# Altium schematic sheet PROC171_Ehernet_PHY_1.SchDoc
size 431 x 279 mm; Date: Not shown in title block; ApprovedBy: Not shown in title block; CheckedBy: Not shown in title block; Author: Not shown in title block; CompanyName: Not shown in title block; Engineer: Not shown in title block; Organization: Not shown in title block; Address1: Not shown in title block; Address2: Not shown in title block; Address3: Not shown in title block; Address4: Not shown in title block; DocumentNumber: 16; Revision: Use project parameter SCH_Rev; SheetNumber: 16; SheetTotal: 26; PageSetup: Record=PageOptions¦CenterHorizontal=True¦CenterVertical=True¦PrintScale=1.00¦XCorrection=1.00¦YCorrection=1.00¦PrintKind=0¦BorderSize=5000000¦LeftOffset=0¦BottomOffset=0¦Orientation=2¦PaperLength=1000¦PaperWidth=1000¦Scale=100¦PaperSource=15¦PrintQuality=600¦MediaType=1¦DitherType=10¦PaperKind=Letter¦PrintScaleMode=1
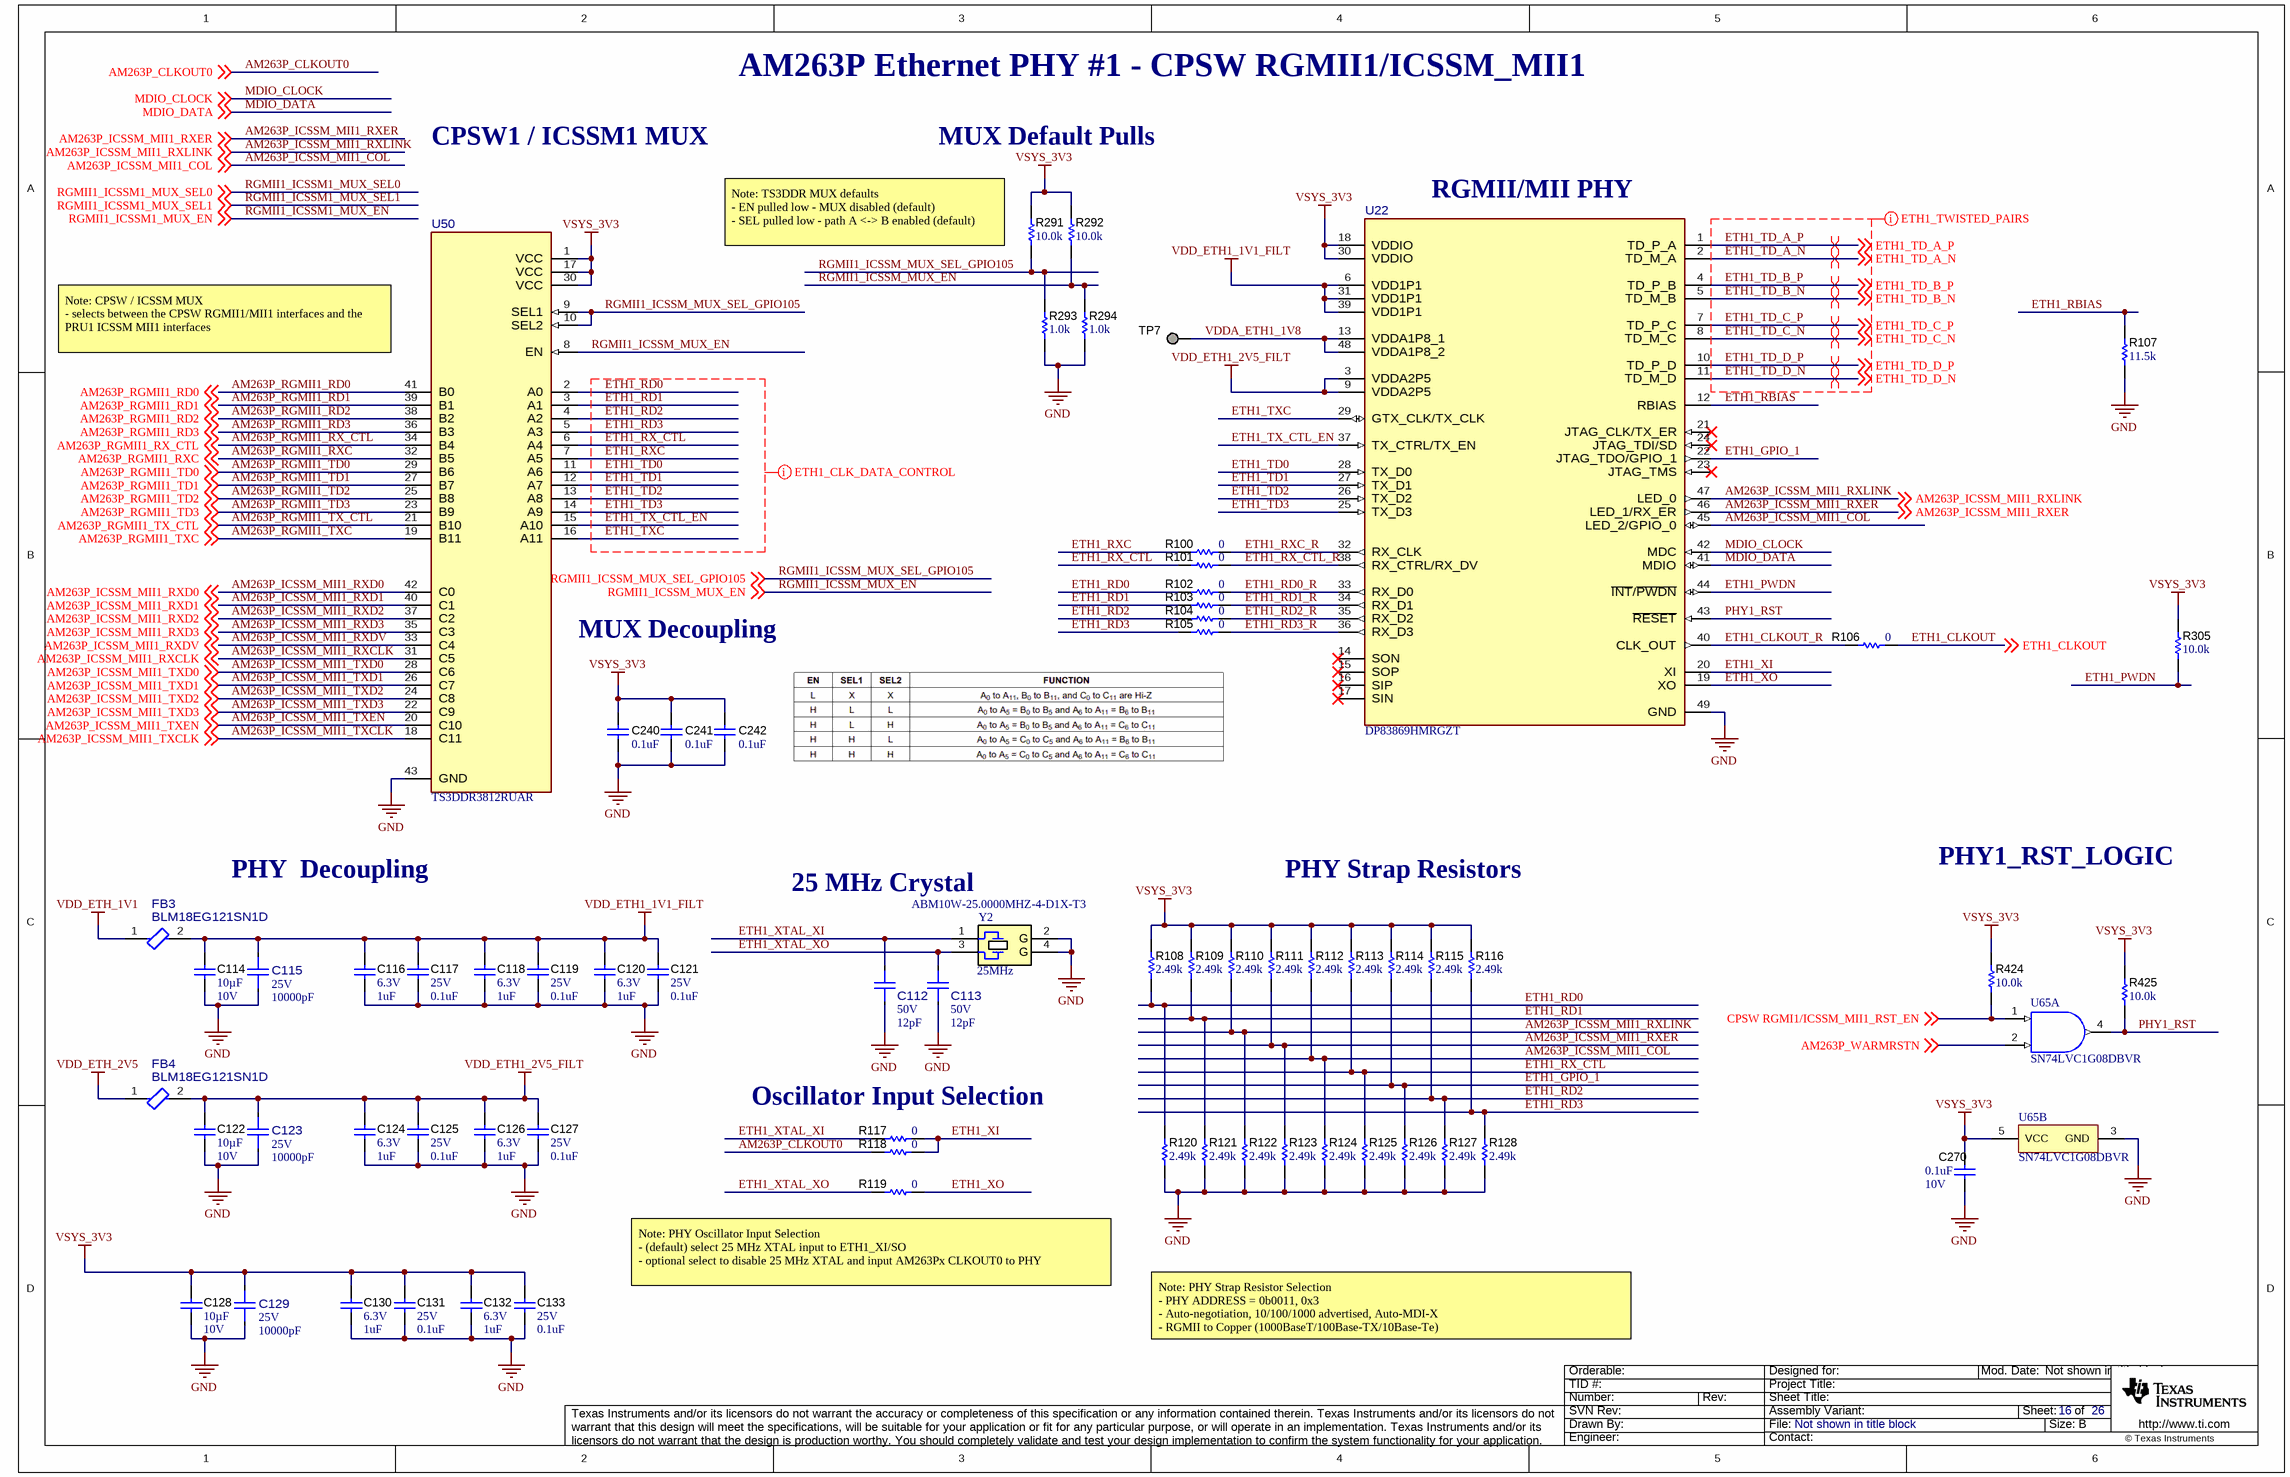
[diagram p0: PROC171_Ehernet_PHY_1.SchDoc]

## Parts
C112  VDC_V: 50V  ValueDisplayed: 12pF  [FP-GJM1555C1H120JB01D_0402-MFG]  (hidden comment: GJM1555C1H120JB01D)
C113  VDC_V: 50V  ValueDisplayed: 12pF  [FP-GJM1555C1H120JB01D_0402-MFG]  (hidden comment: GJM1555C1H120JB01D)
C114  Cap_F: 10µF  VDC_V: 10V  [0603]  (hidden comment: GRM188Z71A106MA73D)
C115  VDC_V: 25V  ValueDisplayed: 10000pF  [FP-GRM1555C1E103JE01D_0402-MFG]  (hidden comment: GRM1555C1E103JE01D)
C116  VDC_V: 6.3V  ValueDisplayed: 1uF  [0402]  (hidden comment: GRM155R70J105MA12D)
C117  VDC_V: 25V  ValueDisplayed: 0.1uF  [0402]  (hidden comment: GRM155R71E104KE14D)
C118  VDC_V: 6.3V  ValueDisplayed: 1uF  [0402]  (hidden comment: GRM155R70J105MA12D)
C119  VDC_V: 25V  ValueDisplayed: 0.1uF  [0402]  (hidden comment: GRM155R71E104KE14D)
C120  VDC_V: 6.3V  ValueDisplayed: 1uF  [0402]  (hidden comment: GRM155R70J105MA12D)
C121  VDC_V: 25V  ValueDisplayed: 0.1uF  [0402]  (hidden comment: GRM155R71E104KE14D)
C122  Cap_F: 10µF  VDC_V: 10V  [0603]  (hidden comment: GRM188Z71A106MA73D)
C123  VDC_V: 25V  ValueDisplayed: 10000pF  [FP-GRM1555C1E103JE01D_0402-MFG]  (hidden comment: GRM1555C1E103JE01D)
C124  VDC_V: 6.3V  ValueDisplayed: 1uF  [0402]  (hidden comment: GRM155R70J105MA12D)
C125  VDC_V: 25V  ValueDisplayed: 0.1uF  [0402]  (hidden comment: GRM155R71E104KE14D)
C126  VDC_V: 6.3V  ValueDisplayed: 1uF  [0402]  (hidden comment: GRM155R70J105MA12D)
C127  VDC_V: 25V  ValueDisplayed: 0.1uF  [0402]  (hidden comment: GRM155R71E104KE14D)
C128  Cap_F: 10µF  VDC_V: 10V  [0603]  (hidden comment: GRM188Z71A106MA73D)
C129  VDC_V: 25V  ValueDisplayed: 10000pF  [FP-GRM1555C1E103JE01D_0402-MFG]  (hidden comment: GRM1555C1E103JE01D)
C130  VDC_V: 6.3V  ValueDisplayed: 1uF  [0402]  (hidden comment: GRM155R70J105MA12D)
C131  VDC_V: 25V  ValueDisplayed: 0.1uF  [0402]  (hidden comment: GRM155R71E104KE14D)
C132  VDC_V: 6.3V  ValueDisplayed: 1uF  [0402]  (hidden comment: GRM155R70J105MA12D)
C133  VDC_V: 25V  ValueDisplayed: 0.1uF  [0402]  (hidden comment: GRM155R71E104KE14D)
C240  ValueDisplayed: 0.1uF  [0402]  (hidden comment: GRM155R71E104KE14D)
C241  ValueDisplayed: 0.1uF  [0402]  (hidden comment: GRM155R71E104KE14D)
C242  ValueDisplayed: 0.1uF  [0402]  (hidden comment: GRM155R71E104KE14D)
C270  VDC_V: 10V  ValueDisplayed: 0.1uF  [0402]  (hidden comment: 885012105010)
FB3  BLM18EG121SN1D  [FP-BLM18EG121SN1D_0603-MFG]
FB4  BLM18EG121SN1D  [FP-BLM18EG121SN1D_0603-MFG]
R100  ValueDisplayed: 0  [0402]  (hidden comment: ERJ-2GE0R00X)
R101  ValueDisplayed: 0  [0402]  (hidden comment: ERJ-2GE0R00X)
R102  ValueDisplayed: 0  [0402]  (hidden comment: ERJ-2GE0R00X)
R103  ValueDisplayed: 0  [0402]  (hidden comment: ERJ-2GE0R00X)
R104  ValueDisplayed: 0  [0402]  (hidden comment: ERJ-2GE0R00X)
R105  ValueDisplayed: 0  [0402]  (hidden comment: ERJ-2GE0R00X)
R106  ValueDisplayed: 0  [0402]  (hidden comment: ERJ-2GE0R00X)
R107  ValueDisplayed: 11.5k  [0402]  (hidden comment: ERJ-2RKF1152X)
R108  ValueDisplayed: 2.49k  [0402]  (hidden comment: CRCW04022K49FKED)
R109  ValueDisplayed: 2.49k  [0402]  (hidden comment: CRCW04022K49FKED)
R110  ValueDisplayed: 2.49k  [0402]  (hidden comment: CRCW04022K49FKED)
R111  ValueDisplayed: 2.49k  [0402]  (hidden comment: CRCW04022K49FKED)
R112  ValueDisplayed: 2.49k  [0402]  (hidden comment: CRCW04022K49FKED)
R113  ValueDisplayed: 2.49k  [0402]  (hidden comment: CRCW04022K49FKED)
R114  ValueDisplayed: 2.49k  [0402]  (hidden comment: CRCW04022K49FKED)
R115  ValueDisplayed: 2.49k  [0402]  (hidden comment: CRCW04022K49FKED)
R116  ValueDisplayed: 2.49k  [0402]  (hidden comment: CRCW04022K49FKED)
R117  ValueDisplayed: 0  [0402]  (hidden comment: ERJ-2GE0R00X)
R118  ValueDisplayed: 0  [0402]  (hidden comment: ERJ-2GE0R00X)
R119  ValueDisplayed: 0  [0402]  (hidden comment: ERJ-2GE0R00X)
R120  ValueDisplayed: 2.49k  [0402]  (hidden comment: CRCW04022K49FKED)
R121  ValueDisplayed: 2.49k  [0402]  (hidden comment: CRCW04022K49FKED)
R122  ValueDisplayed: 2.49k  [0402]  (hidden comment: CRCW04022K49FKED)
R123  ValueDisplayed: 2.49k  [0402]  (hidden comment: CRCW04022K49FKED)
R124  ValueDisplayed: 2.49k  [0402]  (hidden comment: CRCW04022K49FKED)
R125  ValueDisplayed: 2.49k  [0402]  (hidden comment: CRCW04022K49FKED)
R126  ValueDisplayed: 2.49k  [0402]  (hidden comment: CRCW04022K49FKED)
R127  ValueDisplayed: 2.49k  [0402]  (hidden comment: CRCW04022K49FKED)
R128  ValueDisplayed: 2.49k  [0402]  (hidden comment: CRCW04022K49FKED)
R291  ValueDisplayed: 10.0k  [0402]  (hidden comment: ERJ-2RKF1002X)
R292  ValueDisplayed: 10.0k  [0402]  (hidden comment: ERJ-2RKF1002X)
R293  ValueDisplayed: 1.0k  [0402]  (hidden comment: ERJ-2GEJ102X)
R294  ValueDisplayed: 1.0k  [0402]  (hidden comment: ERJ-2GEJ102X)
R305  ValueDisplayed: 10.0k  [0402]  (hidden comment: ERJ-2RKF1002X)
R424  ValueDisplayed: 10.0k  [0402]  (hidden comment: ERJ-2RKF1002X)
R425  ValueDisplayed: 10.0k  [0402L]  (hidden comment: CRCW040210K0FKED)
TP7  TESTPOINT  [TP_25MIL-SMT]  (value not drawn)  (no BOM)
U22  DP83869HMRGZT  [RGZ0048B-MFG]
U50  TS3DDR3812RUAR  [RUA0042A-MFG]
U65  SN74LVC1G08DBVR  [DBV0005A_N]  (parts A,B of 2)
Y2  Frequency_Fixed: 25MHz  [Abracon_ABM10W]  (hidden comment: ABM10W-25.0000MHZ-4-D1X-T3)

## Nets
GND: C112.1 C113.1 C114.2 C115.1 C116.2 C117.2 C118.2 C119.2 C120.2 C121.2 C122.2 C123.1 C124.2 C125.2 C126.2 C127.2 C128.2 C129.1 C130.2 C131.2 C132.2 C133.2 C240.1 C241.1 C242.1 C270.2 R107.1 R120.1 R121.1 R122.1 R123.1 R124.1 R125.1 R126.1 R127.1 R128.1 R293.1 R294.1 U22.49(GND) U50.43(GND) U65.3(GND) Y2.2(GND) Y2.4(GND)
VDD_ETH1_1V1_FILT: C114.1 C115.2 C116.1 C117.1 C118.1 C119.1 C120.1 C121.1 FB3.2 U22.6(VDD1P1) U22.31(VDD1P1) U22.39(VDD1P1)
VDD_ETH1_2V5_FILT: C122.1 C123.2 C124.1 C125.1 C126.1 C127.1 FB4.2 U22.3(VDDA2P5) U22.9(VDDA2P5)
VDD_ETH_1V1: FB3.1
VDD_ETH_2V5: FB4.1
VSYS_3V3: C128.1 C129.2 C130.1 C131.1 C132.1 C133.1 C240.2 C241.2 C242.2 C270.1 R108.2 R109.2 R110.2 R111.2 R112.2 R113.2 R114.2 R115.2 R116.2 R291.1 R292.1 R305.1 R424.1 R425.2 U22.18(VDDIO) U22.30(VDDIO) U50.1(VCC) U50.17(VCC) U50.30(VCC) U65.5(VCC)
AM263P_CLKOUT0: R118.1 ; off-sheet AM263P_CLKOUT0
AM263P_ICSSM_MII1_COL: R112.1 R124.2 U22.45(LED_2/GPIO_0) ; off-sheet AM263P_ICSSM_MII1_COL
AM263P_ICSSM_MII1_RXCLK: U50.31(C5) ; off-sheet AM263P_ICSSM_MII1_RXCLK
AM263P_ICSSM_MII1_RXD0: U50.42(C0) ; off-sheet AM263P_ICSSM_MII1_RXD0
AM263P_ICSSM_MII1_RXD1: U50.40(C1) ; off-sheet AM263P_ICSSM_MII1_RXD1
AM263P_ICSSM_MII1_RXD2: U50.37(C2) ; off-sheet AM263P_ICSSM_MII1_RXD2
AM263P_ICSSM_MII1_RXD3: U50.35(C3) ; off-sheet AM263P_ICSSM_MII1_RXD3
AM263P_ICSSM_MII1_RXDV: U50.33(C4) ; off-sheet AM263P_ICSSM_MII1_RXDV
AM263P_ICSSM_MII1_RXER: R111.1 R123.2 U22.46(LED_1/RX_ER) ; off-sheet AM263P_ICSSM_MII1_RXER
AM263P_ICSSM_MII1_RXLINK: R110.1 R122.2 U22.47(LED_0) ; off-sheet AM263P_ICSSM_MII1_RXLINK
AM263P_ICSSM_MII1_TXCLK: U50.18(C11) ; off-sheet AM263P_ICSSM_MII1_TXCLK
AM263P_ICSSM_MII1_TXD0: U50.28(C6) ; off-sheet AM263P_ICSSM_MII1_TXD0
AM263P_ICSSM_MII1_TXD1: U50.26(C7) ; off-sheet AM263P_ICSSM_MII1_TXD1
AM263P_ICSSM_MII1_TXD2: U50.24(C8) ; off-sheet AM263P_ICSSM_MII1_TXD2
AM263P_ICSSM_MII1_TXD3: U50.22(C9) ; off-sheet AM263P_ICSSM_MII1_TXD3
AM263P_ICSSM_MII1_TXEN: U50.20(C10) ; off-sheet AM263P_ICSSM_MII1_TXEN
AM263P_RGMII1_RD0: U50.41(B0) ; off-sheet AM263P_RGMII1_RD0
AM263P_RGMII1_RD1: U50.39(B1) ; off-sheet AM263P_RGMII1_RD1
AM263P_RGMII1_RD2: U50.38(B2) ; off-sheet AM263P_RGMII1_RD2
AM263P_RGMII1_RD3: U50.36(B3) ; off-sheet AM263P_RGMII1_RD3
AM263P_RGMII1_RX_CTL: U50.34(B4) ; off-sheet AM263P_RGMII1_RX_CTL
AM263P_RGMII1_RXC: U50.32(B5) ; off-sheet AM263P_RGMII1_RXC
AM263P_RGMII1_TD0: U50.29(B6) ; off-sheet AM263P_RGMII1_TD0
AM263P_RGMII1_TD1: U50.27(B7) ; off-sheet AM263P_RGMII1_TD1
AM263P_RGMII1_TD2: U50.25(B8) ; off-sheet AM263P_RGMII1_TD2
AM263P_RGMII1_TD3: U50.23(B9) ; off-sheet AM263P_RGMII1_TD3
AM263P_RGMII1_TX_CTL: U50.21(B10) ; off-sheet AM263P_RGMII1_TX_CTL
AM263P_RGMII1_TXC: U50.19(B11) ; off-sheet AM263P_RGMII1_TXC
AM263P_WARMRSTN: U65.2(B) ; off-sheet AM263P_WARMRSTN
CPSW RGMI1/ICSSM_MII1_RST_EN: R424.2 U65.1(A) ; off-sheet CPSW RGMI1/ICSSM_MII1_RST_EN
ETH1_CLKOUT: R106.2 ; off-sheet ETH1_CLKOUT
ETH1_CLKOUT_R: R106.1 U22.40(CLK_OUT)
ETH1_GPIO_1: R114.1 R126.2 U22.22(JTAG_TDO/GPIO_1)
ETH1_PWDN: R305.2 U22.44(~{INT}/~{PWDN})
ETH1_RBIAS: R107.2 U22.12(RBIAS)
ETH1_RD0: R102.1 R108.1 R120.2 U50.2(A0)
ETH1_RD0_R: R102.2 U22.33(RX_D0)
ETH1_RD1: R103.1 R109.1 R121.2 U50.3(A1)
ETH1_RD1_R: R103.2 U22.34(RX_D1)
ETH1_RD2: R104.1 R115.1 R127.2 U50.4(A2)
ETH1_RD2_R: R104.2 U22.35(RX_D2)
ETH1_RD3: R105.1 R116.1 R128.2 U50.5(A3)
ETH1_RD3_R: R105.2 U22.36(RX_D3)
ETH1_RX_CTL: R101.1 R113.1 R125.2 U50.6(A4)
ETH1_RX_CTL_R: R101.2 U22.38(RX_CTRL/RX_DV)
ETH1_RXC: R100.1 U50.7(A5)
ETH1_RXC_R: R100.2 U22.32(RX_CLK)
ETH1_TD0: U22.28(TX_D0) U50.11(A6)
ETH1_TD1: U22.27(TX_D1) U50.12(A7)
ETH1_TD2: U22.26(TX_D2) U50.13(A8)
ETH1_TD3: U22.25(TX_D3) U50.14(A9)
ETH1_TD_A_N: U22.2(TD_M_A) ; off-sheet ETH1_TD_A_N
ETH1_TD_A_P: U22.1(TD_P_A) ; off-sheet ETH1_TD_A_P
ETH1_TD_B_N: U22.5(TD_M_B) ; off-sheet ETH1_TD_B_N
ETH1_TD_B_P: U22.4(TD_P_B) ; off-sheet ETH1_TD_B_P
ETH1_TD_C_N: U22.8(TD_M_C) ; off-sheet ETH1_TD_C_N
ETH1_TD_C_P: U22.7(TD_P_C) ; off-sheet ETH1_TD_C_P
ETH1_TD_D_N: U22.11(TD_M_D) ; off-sheet ETH1_TD_D_N
ETH1_TD_D_P: U22.10(TD_P_D) ; off-sheet ETH1_TD_D_P
ETH1_TX_CTL_EN: U22.37(TX_CTRL/TX_EN) U50.15(A10)
ETH1_TXC: U22.29(GTX_CLK/TX_CLK) U50.16(A11)
ETH1_XI: R117.2 R118.2 U22.20(XI)
ETH1_XO: R119.2 U22.19(XO)
ETH1_XTAL_XI: C112.2 R117.1 Y2.1
ETH1_XTAL_XO: C113.2 R119.1 Y2.3
MDIO_CLOCK: U22.42(MDC) ; off-sheet MDIO_CLOCK
MDIO_DATA: U22.41(MDIO) ; off-sheet MDIO_DATA
PHY1_RST: R425.1 U22.43(~{RESET}) U65.4(Y)
RGMII1_ICSSM_MUX_EN: R292.2 R294.2 U50.8(EN) ; off-sheet RGMII1_ICSSM_MUX_EN
RGMII1_ICSSM_MUX_SEL_GPIO105: R291.2 R293.2 U50.9(SEL1) U50.10(SEL2) ; off-sheet RGMII1_ICSSM_MUX_SEL_GPIO105
VDDA_ETH1_1V8: TP7.1 U22.13(VDDA1P8_1) U22.48(VDDA1P8_2)

Not connected (* = marked no-connect by the designer): U22 14(SON)* 15(SOP)* 16(SIP)* 17(SIN)* 21(JTAG_CLK/TX_ER)* 23(JTAG_TMS)* 24(JTAG_TDI/SD)*

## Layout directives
differential pair: ETH1_TD_A_N, ETH1_TD_A_P, ETH1_TD_B_N, ETH1_TD_B_P, ETH1_TD_C_N, ETH1_TD_C_P, ETH1_TD_D_N, ETH1_TD_D_P
mark named ETH1_TWISTED_PAIRS: ETH1_TD_A_N, ETH1_TD_A_P, ETH1_TD_B_N, ETH1_TD_B_P, ETH1_TD_C_N, ETH1_TD_C_P, ETH1_TD_D_N, ETH1_TD_D_P
mark named ETH1_CLK_DATA_CONTROL: ETH1_RD0, ETH1_RD1, ETH1_RD2, ETH1_RD3, ETH1_RX_CTL, ETH1_RXC, ETH1_TD0, ETH1_TD1, ETH1_TD2, ETH1_TD3, ETH1_TX_CTL_EN, ETH1_TXC

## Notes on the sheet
- AM263P Ethernet PHY #1 - CPSW RGMII1/ICSSM_MII1
- CPSW1 / ICSSM1 MUX
- MUX Default Pulls
- (near U22) RGMII/MII PHY
- (near R291) Note: TS3DDR MUX defaults
  - EN pulled low - MUX disabled (default)
  - SEL pulled low - path A <-> B enabled (default)
- (near U50) Note: CPSW / ICSSM MUX
  - selects between the CPSW RGMII1/MII1 interfaces and the PRU1 ICSSM MII1 interfaces
- (near U50) MUX Decoupling
- PHY  Decoupling
- (near Y2) 25 MHz Crystal
- PHY Strap Resistors
- PHY1_RST_LOGIC
- Oscillator Input Selection
- (near R119) Note: PHY Oscillator Input Selection
  - (default) select 25 MHz XTAL input to ETH1_XI/SO
  - optional select to disable 25 MHz XTAL and input AM263Px CLKOUT0 to PHY
- Note: PHY Strap Resistor Selection
  - PHY ADDRESS = 0b0011, 0x3
  - Auto-negotiation, 10/100/1000 advertised, Auto-MDI-X
  - RGMII to Copper (1000BaseT/100Base-TX/10Base-Te)

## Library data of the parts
C112 C113 = CMP-0035228-1: Multi-Layer Ceramic Capacitor 12pF C0G  ±5% 0402 Paper T/R; Manufacturer: Murata; TempCo: 30ppm/°C; SizeZ_mm: 0.55mm; AEC Qualified: No
C114 C122 C128 = CMP-0007497-5: CAP, CERM, 10 uF, 10 V, +/- 20%, X7R, 0603; Manufacturer: MuRata; TaMin_C: -55°C; Polarized: N; SizeAreaWB_mm2: 4.68; Value1: Unknown; U/M: EA; Value: 10uF; TaMax_C: 125°C; SizeZ_mm: 1; SizeX_mm: 1.6; SizeY_mm: 0.8; SizeArea_mm2: 1.28; AEC Category: Q200
C115 C123 C129 = CMP-0035343-1: Chip Multilayer Ceramic Capacitors for General Purpose, 0402, 10000pF, C0G, 30ppm/°C, 5%, 25V; Manufacturer: Murata; Value: 10nF; SizeZ_mm: 0.65mm; AEC Qualified: No
C116 C118 C120 C124 C126 C130 C132 = CMP-0006624-2: CAP, CERM, 1 uF, 6.3 V, +/- 20%, X7R, 0402; Manufacturer: MuRata; TaMin_C: -55°C; Polarized: N; SizeAreaWB_mm2: 3; Value1: Unknown; U/M: EA; Value: 1uF; TaMax_C: 125°C; SizeZ_mm: 0.6; SizeX_mm: 1; SizeY_mm: 0.5; Cap_F: 1µF; AEC Category: Q200
C117 C119 C121 C125 C127 C131 C133 = CMP-0006659-2: CAP, CERM, 0.1 uF, 25 V, +/- 10%, X7R, 0402; Manufacturer: MuRata; TaMin_C: -55°C; Polarized: N; SizeAreaWB_mm2: 3; Value1: Unknown; U/M: EA; Value: 0.1uF; TaMax_C: 125°C; SizeZ_mm: 0.6; SizeX_mm: 1; SizeY_mm: 0.5; Cap_F: 100nF; AEC Category: Q200
C240-C242 = CMP-0006659-2: CAP, CERM, 0.1 uF, 25 V, +/- 10%, X7R, 0402; Manufacturer: MuRata; TaMin_C: -55°C; Polarized: N; SizeAreaWB_mm2: 3; U/M: EA; Value: 0.1uF; TaMax_C: 125°C; SizeZ_mm: 0.6; SizeX_mm: 1; SizeY_mm: 0.5; Value2: 25V; Cap_F: 100nF; AEC Category: Q200; Value1: Unknown
C270 = CMP-0006221-2: CAP, CERM, 0.1 uF, 10 V, +/- 20%, X5R, 0402; Manufacturer: Wurth Elektronik; TaMin_C: -55°C; Polarized: N; SizeAreaWB_mm2: 3; Value1: Unknown; U/M: EA; Value: 0.1uF; TaMax_C: 85°C; SizeZ_mm: 0.6; SizeX_mm: 1; SizeY_mm: 0.5; Cap_F: 100nF; AEC Category: Q200
FB3 FB4 = CMP-0089199-1: 120 Ohms @ 100MHz 1  Ferrite Bead 0603 (1608 Metric) 2A 40mOhm; Manufacturer: Murata; DCR_ohm: 60m; AEC Qualified: No; Tolerance_%: 25%; SizeZ_mm: 0.95mm; Impedance At Frequency: 120Ω @ 100MHz
R100-R106 R117-R119 = CMP-0026992-3: RES, 0, 5%, 0.1 W, AEC-Q200 Grade 0, 0402; Manufacturer: Panasonic; Power_W: 100mW; TempCo: 600 ppm/C; Value_Code: 0000; Value: 0; EIA_Code: E24; SizeX_mm: 1; SizeY_mm: 0.5; SizeZ_mm: 0.6; Value2: 0.1W; AEC Qualified: Y; VDC_V: 50V; AEC Category: Q200; SizeAreaWB_mm2: 3
R107 = CMP-0082348-1: RES, 11.5 k, 1%, 0.1 W, AEC-Q200 Grade 0, 0402; Manufacturer: Panasonic; Value_Code: 11k5; SizeAreaWB_mm2: 3; SizeArea_mm2: 0.5; AEC Qualified: Y; AEC Category: Q200; Value: 11.5k; SizeZ_mm: 0.6; EIA_Code: E96; TempCo: 100 ppm/C; AEC Grade: 0; Power_W: 100mW; Value2: 0.1W; SizeX_mm: 1
R108-R116 R120-R128 = CMP-0026237-2: RES, 2.49 k, 1%, 0.063 W, AEC-Q200 Grade 0, 0402; Manufacturer: Vishay-Dale; Power_W: 63mW; TempCo: 100 ppm/C; Value_Code: 2k49; Value: 2.49k; EIA_Code: E96; SizeX_mm: 1; SizeY_mm: 0.5; SizeZ_mm: 0.6; Value2: 0.063W; AEC Qualified: Y; VDC_V: 50V; AEC Category: Q200; AEC Grade: 0
R291 R292 R305 R424 = CMP-0026658-1: RES, 10.0 k, 1%, 0.1 W, 0402; Manufacturer: Panasonic; Power_W: 100mW; TempCo: 100 ppm/C; Value_Code: 10k0; U/M: EA; Value: 10.0k; EIA_Code: E96; Res_ohm: 10k; SizeX_mm: 1; SizeY_mm: 0.5; SizeZ_mm: 0.6; Value2: 0.1W; VDC_V: 50V; AEC Category: Q200
R293 R294 = CMP-0078193-1: RES, 1.0 k, 5%, 0.1 W, AEC-Q200 Grade 0, 0402; Manufacturer: Panasonic; Value_Code: 1k00; SizeArea_mm2: 0.5; AEC Qualified: Y; AEC Category: Q200; Res_ohm: 1k; Value: 1.0k; SizeZ_mm: 0.6; Green_REACh: Passed; EIA_Code: E24; TempCo: 200 ppm/C; AEC Grade: 0; Power_W: 100mW; VDC_V: 50V; Value2: 0.1W; Green_Lifecycle: Active; U/M: EA; SizeX_mm: 1
R425 = CMP-0025958-3: RES, 10.0 k, 1%, 0.063 W, AEC-Q200 Grade 0, 0402; Manufacturer: Vishay-Dale; Power_W: 63mW; TempCo: 100 ppm/C; Value_Code: 10k0; Value: 10.0k; EIA_Code: E96; Res_ohm: 10k; SizeX_mm: 1; SizeY_mm: 0.5; SizeZ_mm: 0.6; Value2: 0.063W; AEC Qualified: Y; VDC_V: 50V; AEC Category: Q200; AEC Grade: 0
TP7 = CMP-0078143-3: TEST POINT.  No entry in BOM.
U22 = CMP-0091377-1: 1/1 Transceiver Ethernet 48-VQFN (7x7); Manufacturer: Texas Instruments; TaMin_C: -40°C; SizeZ_mm: 1mm; TaMax_C: +125°C; Max Supply Voltage: 3.45V; Number Of Channels: 1; AEC Qualified: No; Data Rate: 1000Mbits/s; Min Supply Voltage: 990mV; Simplex Duplex: Full-Duplex; Standoff Height: 0mm
U50 = CMP-0093539-2: IC MUX/DEMUX DDR3 1:2 42WQFN; Manufacturer: Texas Instruments; TaMax_C: +85°C; TaMin_C: -40°C; On State Resistance: 8Ω; SizeZ_mm: 0.8mm; Min Supply Voltage: 3V; Standoff Height: 0mm; Max Supply Voltage: 3.6V; AEC Qualified: No; PositionCount: 12; -3Db Bandwith: 1.675GHz; Nominal Supply Current: 300uA; AEC Category: Q200
U65 = CMP-0051588-2: Single 2-Input Positive-AND Gate, DBV0005A, LARGE T&R; Manufacturer: Texas Instruments; Logic: True; ICC @ Nom Voltage(Max)(mA): 0.01; VCC(Min)(V): 1.65; Bits(#): 1; Rating: Catalog; Schmitt Trigger: No; Voltage(Nom)(V): 1.8,2.5,3.3,5; Output Drive (IOL/IOH)(Max)(mA): 32/-32; Gate Type: AND; tpd @ Nom Voltage(Max)(ns): 4.5,6,4,5; VCC(Max)(V): 5.5; Output Type: CMOS; F @ Nom Voltage(Max)(Mhz): 150; Input Type: CMOS/TTL; Technology Family: LVC; AEC Category: Q200; AEC Qualified: N; CompType: IC
Y2 = CMP-0084811-1: Crystal, 25 MHz, 10 ppm, 4 pF, SMD; Manufacturer: Abracon Corporation; Load Capacitance: 4 pF; TaMax_C: 85°C; SizeY_mm: 2.5; SizeAreaWB_mm2: 10.5; AEC Category: Q200; Frequency Stability: 20 ppm; SizeX_mm: 2; SizeArea_mm2: 5; SizeZ_mm: 0.6; AEC Qualified: N; TaMin_C: -40°C; Frequency Tolerance: 10 ppm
